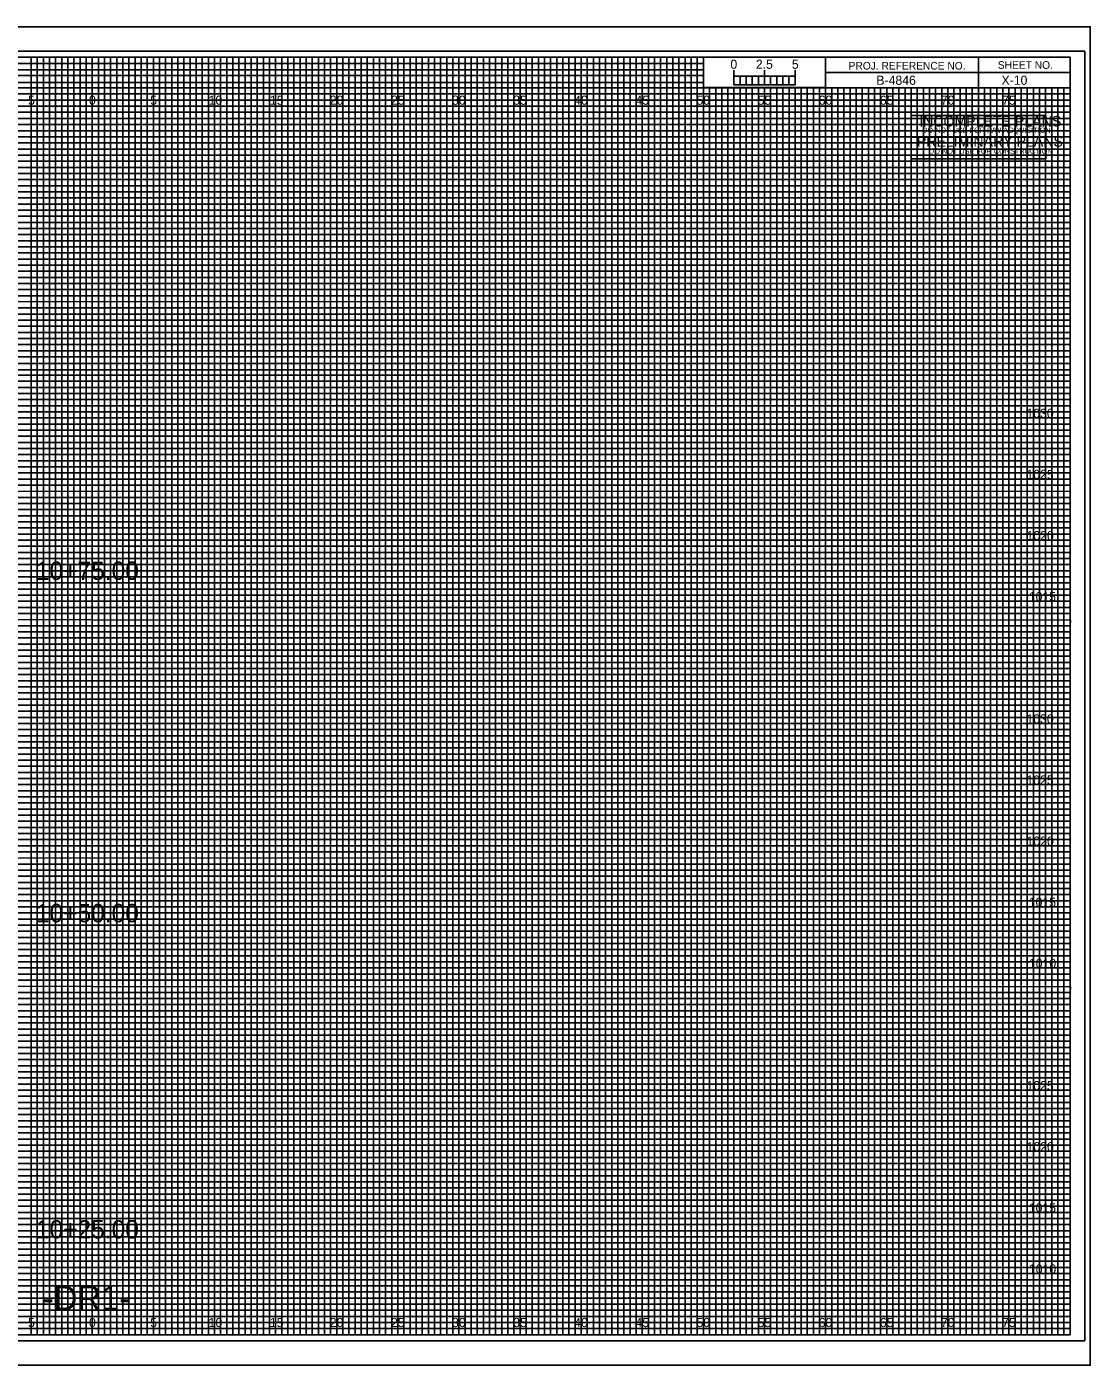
# Model space of a CAD drawing. Extents: x -7 to 162, y -2 to 107.
# Drawn here: x 74.6 to 161.7, y -2.5 to 107 of the extents above; entities that cross this region are included whole.
import ezdxf

# ---------------------------------------------------------------- set-up
doc = ezdxf.new("R2010")
doc.units = 0
for name, color, linetype in [('Default', 7, 'Continuous'), ('Exist Cross Section Cell', 7, 'Continuous'), ('Exist XS Center Line Elevation Label', 7, 'Continuous'), ('Exist XS Ground Line', 7, 'Continuous'), ('Prop CMT Concrete Structures', 7, 'Continuous'), ('Prop CMT DNC', 7, 'Continuous'), ('Prop CMT Guardrail Graphics', 7, 'Continuous'), ('Prop CMT Guardrail Widen Shoulder', 7, 'Continuous'), ('Prop CMT Pvmt Course 1', 7, 'Continuous'), ('Prop CMT Pvmt Surface', 7, 'Continuous'), ('Prop CMT Pvmt Surface Shoulder', 7, 'Continuous'), ('Prop CMT Shld Paved Course 1', 7, 'Continuous'), ('Prop CMT Shoulder Point', 7, 'Continuous'), ('Prop CMT Slope Grass', 7, 'Continuous'), ('Prop CMT Subgrade Earthwork', 7, 'Continuous'), ('Prop XS SE Text', 7, 'Continuous'), ('Prop XS Side Slope Text', 7, 'Continuous'), ('Typical Text Label CELL', 7, 'Continuous')]:
    doc.layers.add(name, color=color, linetype=linetype)

msp = doc.modelspace()

# ---------------------------------------------------------------- linework, layer by layer
at = {"layer": 'Default'}
for points in [[(146.99, 97.97), (146.99, 99.73), (158.01, 99.73), (158.01, 97.97)], [(146.99, 96.2), (146.99, 97.97), (158.01, 97.97), (158.01, 96.2)]]:
    msp.add_lwpolyline(points, close=True, dxfattribs=at)
at = {"layer": 'Exist XS Center Line Elevation Label'}
for points in [[(72.5, 0), (77.5, 0), (77.5, 104.5), (82.5, 104.5), (82.5, 0), (87.5, 0), (87.5, 104.5), (92.5, 104.5), (92.5, 0), (97.5, 0), (97.5, 104.5), (102.5, 104.5), (102.5, 0), (107.5, 0), (107.5, 104.5), (112.5, 104.5), (112.5, 0), (117.5, 0), (117.5, 104.5), (122.5, 104.5), (122.5, 0), (127.5, 0), (127.5, 104.5), (129.97, 104.5), (130, 104.5), (130, 102), (132.5, 102), (132.5, 0), (137.5, 0), (137.5, 102), (142.5, 102), (142.5, 0), (147.5, 0), (147.5, 102), (152.5, 102), (152.5, 0), (157.5, 0), (157.5, 102)], [(0, 102), (137.5, 102)], [(0, 92.5), (160, 92.5), (160, 97.5), (0, 97.5)], [(0, 82.5), (160, 82.5), (160, 87.5), (0, 87.5)], [(0, 72.5), (160, 72.5), (160, 77.5), (0, 77.5)], [(0, 62.5), (160, 62.5), (160, 67.5), (0, 67.5)], [(0, 52.5), (160, 52.5), (160, 57.5), (0, 57.5)], [(0, 42.5), (160, 42.5), (160, 47.5), (0, 47.5)], [(0, 32.5), (160, 32.5), (160, 37.5), (0, 37.5)], [(0, 22.5), (160, 22.5), (160, 27.5), (0, 27.5)], [(0, 12.5), (160, 12.5), (160, 17.5), (0, 17.5)], [(0, 2.5), (160, 2.5), (160, 7.5), (0, 7.5)]]:
    msp.add_lwpolyline(points, dxfattribs=at)
at = {"layer": 'Exist XS Ground Line'}
for p, q in [((75, 104.5), (70, 104.5)), ((75, 0), (75, 104.5)), ((85, 104.5), (80, 104.5)), ((80, 104.5), (80, 0)), ((85, 0), (85, 104.5)), ((95, 104.5), (90, 104.5)), ((90, 104.5), (90, 0)), ((95, 0), (95, 104.5)), ((105, 104.5), (100, 104.5)), ((100, 104.5), (100, 0)), ((105, 0), (105, 104.5)), ((115, 104.5), (110, 104.5)), ((110, 104.5), (110, 0)), ((115, 0), (115, 104.5)), ((125, 104.5), (120, 104.5)), ((120, 104.5), (120, 0)), ((125, 0), (125, 104.5)), ((130, 104.5), (130, 0)), ((135, 0), (135, 102)), ((145, 102), (140, 102)), ((140, 102), (140, 0)), ((145, 0), (145, 102)), ((155, 102), (150, 102)), ((150, 102), (150, 0)), ((155, 0), (155, 102)), ((80, 0), (75, 0)), ((90, 0), (85, 0)), ((100, 0), (95, 0)), ((110, 0), (105, 0)), ((120, 0), (115, 0)), ((130, 0), (125, 0)), ((140, 0), (135, 0)), ((150, 0), (145, 0)), ((160, 0), (155, 0)), ((160, 0), (160, 0))]:
    msp.add_line(p, q, dxfattribs=at)
for points in [[(0, 100), (160, 100), (160, 95), (0, 95)], [(0, 90), (160, 90), (160, 85), (0, 85)], [(0, 80), (160, 80), (160, 75), (0, 75)], [(0, 70), (160, 70), (160, 65), (0, 65)], [(0, 60), (160, 60), (160, 55), (0, 55)], [(0, 50), (160, 50), (160, 45), (0, 45)], [(0, 40), (160, 40), (160, 35), (0, 35)], [(0, 30), (160, 30), (160, 25), (0, 25)], [(0, 20), (160, 20), (160, 15), (0, 15)], [(0, 10), (160, 10), (160, 5), (0, 5)]]:
    msp.add_lwpolyline(points, dxfattribs=at)
at = {"layer": 'Prop CMT Concrete Structures'}
for p, q in [((75, 0), (75, 104.5)), ((80, 0), (80, 104.5)), ((85, 0), (85, 104.5)), ((90, 0), (90, 104.5)), ((95, 0), (95, 104.5)), ((100, 0), (100, 104.5)), ((105, 0), (105, 104.5)), ((110, 0), (110, 104.5)), ((115, 0), (115, 104.5)), ((120, 0), (120, 104.5)), ((125, 0), (125, 104.5)), ((130, 0), (130, 101.84)), ((135, 0), (135, 101.84)), ((140, 0), (140, 101.84)), ((145, 0), (145, 101.84)), ((150, 0), (150, 101.84)), ((155, 0), (155, 101.84)), ((0, 100), (160, 100)), ((0, 95), (160, 95)), ((0, 90), (160, 90)), ((0, 85), (160, 85)), ((0, 80), (160, 80)), ((0, 75), (160, 75)), ((0, 70), (160, 70)), ((0, 65), (160, 65)), ((0, 60), (160, 60)), ((0, 55), (160, 55)), ((0, 50), (160, 50)), ((0, 45), (160, 45)), ((0, 40), (160, 40)), ((0, 35), (160, 35)), ((0, 30), (160, 30)), ((0, 25), (160, 25)), ((0, 20), (160, 20)), ((0, 15), (160, 15)), ((0, 10), (160, 10)), ((0, 5), (160, 5))]:
    msp.add_line(p, q, dxfattribs=at)
at = {"layer": 'Prop CMT Guardrail Widen Shoulder'}
for p, q in [((161.65, 107), (-6.7, 107)), ((-6.7, -2.5), (161.65, -2.5))]:
    msp.add_line(p, q, dxfattribs=at)
at = {"layer": 'Prop CMT Pvmt Course 1'}
msp.add_lwpolyline([(-6.7, -2.5), (161.65, -2.5), (161.65, 107), (-6.7, 107)], close=True, dxfattribs=at)
at = {"layer": 'Prop CMT Pvmt Surface'}
for p, q in [((133.5, 102), (133, 102)), ((133, 102), (133, 0)), ((133.5, 0), (133.5, 102)), ((134.5, 102), (134, 102)), ((134, 102), (134, 0)), ((134.5, 0), (134.5, 102)), ((133, 0), (132.5, 0)), ((134, 0), (133.5, 0))]:
    msp.add_line(p, q, dxfattribs=at)
for points in [[(75, 0), (75.5, 0), (75.5, 104.5), (76, 104.5), (76, 0)], [(76, 0), (76.5, 0), (76.5, 104.5), (77, 104.5), (77, 0)], [(77.5, 0), (78, 0), (78, 104.5), (78.5, 104.5), (78.5, 0)], [(78.5, 0), (79, 0), (79, 104.5), (79.5, 104.5), (79.5, 0)], [(80, 0), (80.5, 0), (80.5, 104.5), (81, 104.5), (81, 0)], [(81, 0), (81.5, 0), (81.5, 104.5), (82, 104.5), (82, 0)], [(82.5, 0), (83, 0), (83, 104.5), (83.5, 104.5), (83.5, 0)], [(83.5, 0), (84, 0), (84, 104.5), (84.5, 104.5), (84.5, 0)], [(85, 0), (85.5, 0), (85.5, 104.5), (86, 104.5), (86, 0)], [(86, 0), (86.5, 0), (86.5, 104.5), (87, 104.5), (87, 0)], [(87.5, 0), (88, 0), (88, 104.5), (88.5, 104.5), (88.5, 0)], [(88.5, 0), (89, 0), (89, 104.5), (89.5, 104.5), (89.5, 0)], [(90, 0), (90.5, 0), (90.5, 104.5), (91, 104.5), (91, 0)], [(91, 0), (91.5, 0), (91.5, 104.5), (92, 104.5), (92, 0)], [(92.5, 0), (93, 0), (93, 104.5), (93.5, 104.5), (93.5, 0)], [(93.5, 0), (94, 0), (94, 104.5), (94.5, 104.5), (94.5, 0)], [(95, 0), (95.5, 0), (95.5, 104.5), (96, 104.5), (96, 0)], [(96, 0), (96.5, 0), (96.5, 104.5), (97, 104.5), (97, 0)], [(97.5, 0), (98, 0), (98, 104.5), (98.5, 104.5), (98.5, 0)], [(98.5, 0), (99, 0), (99, 104.5), (99.5, 104.5), (99.5, 0)], [(100, 0), (100.5, 0), (100.5, 104.5), (101, 104.5), (101, 0)], [(101, 0), (101.5, 0), (101.5, 104.5), (102, 104.5), (102, 0)], [(102.5, 0), (103, 0), (103, 104.5), (103.5, 104.5), (103.5, 0)], [(103.5, 0), (104, 0), (104, 104.5), (104.5, 104.5), (104.5, 0)], [(105, 0), (105.5, 0), (105.5, 104.5), (106, 104.5), (106, 0)], [(106, 0), (106.5, 0), (106.5, 104.5), (107, 104.5), (107, 0)], [(107.5, 0), (108, 0), (108, 104.5), (108.5, 104.5), (108.5, 0)], [(108.5, 0), (109, 0), (109, 104.5), (109.5, 104.5), (109.5, 0)], [(110, 0), (110.5, 0), (110.5, 104.5), (111, 104.5), (111, 0)], [(111, 0), (111.5, 0), (111.5, 104.5), (112, 104.5), (112, 0)], [(112.5, 0), (113, 0), (113, 104.5), (113.5, 104.5), (113.5, 0)], [(113.5, 0), (114, 0), (114, 104.5), (114.5, 104.5), (114.5, 0)], [(115, 0), (115.5, 0), (115.5, 104.5), (116, 104.5), (116, 0)], [(116, 0), (116.5, 0), (116.5, 104.5), (117, 104.5), (117, 0)], [(117.5, 0), (118, 0), (118, 104.5), (118.5, 104.5), (118.5, 0)], [(118.5, 0), (119, 0), (119, 104.5), (119.5, 104.5), (119.5, 0)], [(120, 0), (120.5, 0), (120.5, 104.5), (121, 104.5), (121, 0)], [(121, 0), (121.5, 0), (121.5, 104.5), (122, 104.5), (122, 0)], [(122.5, 0), (123, 0), (123, 104.5), (123.5, 104.5), (123.5, 0)], [(123.5, 0), (124, 0), (124, 104.5), (124.5, 104.5), (124.5, 0)], [(125, 0), (125.5, 0), (125.5, 104.5), (126, 104.5), (126, 0)], [(126, 0), (126.5, 0), (126.5, 104.5), (127, 104.5), (127, 0)], [(127.5, 0), (128, 0), (128, 104.5), (128.5, 104.5), (128.5, 0)], [(128.5, 0), (129, 0), (129, 104.5), (129.5, 104.5), (129.5, 0)], [(130, 0), (130.5, 0), (130.5, 102), (131.01, 102), (131.01, 0)], [(131, 0), (131.5, 0), (131.5, 102), (132, 102), (132, 0)], [(135, 0), (135.49, 0), (135.49, 102), (136, 102), (136, 0)], [(136, 0), (136.5, 0), (136.5, 102), (137.03, 102), (137.03, 0)], [(137.5, 0), (138, 0), (138, 102), (138.5, 102), (138.5, 0)], [(138.5, 0), (139, 0), (139, 102), (139.5, 102), (139.5, 0)], [(140, 0), (140.5, 0), (140.5, 102), (141, 102), (141, 0)], [(141, 0), (141.5, 0), (141.5, 102), (142, 102), (142, 0)], [(142.5, 0), (143, 0), (143, 102), (143.5, 102), (143.5, 0)], [(143.5, 0), (144, 0), (144, 102), (144.5, 102), (144.5, 0)], [(145, 0), (145.5, 0), (145.5, 102), (146, 102), (146, 0)], [(146, 0), (146.5, 0), (146.5, 102), (147, 102), (147, 0)], [(147.5, 0), (148, 0), (148, 102), (148.5, 102), (148.5, 0)], [(148.5, 0), (149, 0), (149, 102), (149.5, 102), (149.5, 0)], [(150, 0), (150.5, 0), (150.5, 102), (151, 102), (151, 0)], [(151, 0), (151.5, 0), (151.5, 102), (152, 102), (152, 0)], [(152.5, 0), (153, 0), (153, 102), (153.5, 102), (153.5, 0)], [(153.5, 0), (154, 0), (154, 102), (154.5, 102), (154.5, 0)], [(155, 0), (155.5, 0), (155.5, 102), (156, 102), (156, 0)], [(156, 0), (156.5, 0), (156.5, 102), (157, 102), (157, 0)], [(157.5, 0), (158, 0), (158, 102), (158.5, 102), (158.5, 0)], [(158.5, 0), (159, 0), (159, 102), (159.5, 102), (159.5, 0)]]:
    msp.add_lwpolyline(points, dxfattribs=at)
at = {"layer": 'Prop CMT Pvmt Surface Shoulder'}
for p, q in [((132.5, 102.25), (132.5, 103.45)), ((132.5, 102.95), (132.5, 103.45)), ((135, 102.25), (135, 103.45)), ((137.5, 102.25), (137.5, 103.45)), ((137.5, 102.95), (137.5, 103.45))]:
    msp.add_line(p, q, dxfattribs=at)
for points in [[(137.5, 102.95), (132.5, 102.95), (132.5, 102.25), (137.5, 102.25)], [(132.5, 102.95), (133, 102.95), (133, 102.25), (132.5, 102.25)], [(133.5, 102.95), (134, 102.95), (134, 102.25), (133.5, 102.25)], [(134.5, 102.95), (135, 102.95), (135, 102.25), (134.5, 102.25)], [(135.5, 102.95), (136, 102.95), (136, 102.25), (135.5, 102.25)], [(136.5, 102.95), (137, 102.95), (137, 102.25), (136.5, 102.25)]]:
    msp.add_lwpolyline(points, close=True, dxfattribs=at)
at = {"layer": 'Prop CMT Shld Paved Course 1'}
for p, q in [((0, 104), (130, 104)), ((130, 103.49), (0, 103.49)), ((0, 103), (130, 103)), ((130, 104), (130, 103.49)), ((130, 103), (130, 102.45)), ((130, 102.45), (0, 102.45)), ((0, 101.5), (160, 101.5))]:
    msp.add_line(p, q, dxfattribs=at)
for points in [[(0, 101), (135, 101), (160, 101), (160, 101), (0, 101)], [(0, 100.5), (160, 100.5), (160, 99.5), (0, 99.5)], [(0, 99), (160, 99), (160, 98.5), (0, 98.49)], [(0, 98), (160, 98), (160, 97), (0, 97)], [(0, 96.5), (160, 96.5), (160, 96), (0, 96)], [(0, 95.5), (160, 95.5), (160, 94.5), (0, 94.5)], [(0, 94), (160, 94), (160, 93.5), (0, 93.5)], [(0, 93), (160, 93), (160, 92), (0, 92)], [(0, 91.5), (160, 91.5), (160, 91), (0, 91)], [(0, 90.5), (160, 90.5), (160, 89.5), (0, 89.5)], [(0, 89), (160, 89), (160, 88.5), (0, 88.5)], [(0, 88), (160, 88), (160, 86.98), (160, 86.5), (160, 86), (0, 86)], [(0, 87), (160, 87), (160, 86.5), (0, 86.5)], [(0, 85.5), (160, 85.5), (160, 84.5), (0, 84.52)], [(0, 84.52), (160, 84.5), (160, 84), (0, 84)], [(0, 83.5), (160, 83.5), (160, 83), (0, 83)], [(0, 82), (160, 82), (160, 81.5), (0, 81.5)], [(0, 81), (160, 81), (160, 80.5), (0, 80.5)], [(-0.04, 79.45), (160, 79.45), (160, 78.94), (-0.04, 78.94)], [(0, 78.5), (160, 78.5), (160, 78), (0, 78)], [(0, 77), (160, 77), (160, 76.5), (0, 76.5)], [(0, 76), (160, 76), (160, 75.5), (0, 75.5)], [(0, 74.5), (160, 74.5), (160, 74), (0, 74)], [(0, 73.5), (160, 73.5), (160, 73), (0, 73)], [(0, 72), (160, 72), (160, 71.5), (0, 71.5)], [(0, 71), (160, 71), (160, 70.5), (0, 70.5)], [(0, 69.5), (160, 69.5), (160, 68.99), (0, 69)], [(0, 68.5), (160, 68.5), (160, 68), (0, 68)], [(0, 67), (160, 67), (160, 66.5), (0, 66.5)], [(0, 66), (160, 66), (160, 65.5), (0, 65.5)], [(0, 64.5), (160, 64.5), (160, 64), (0, 64)], [(0, 63.5), (160, 63.5), (160, 63), (0, 63)], [(0, 62), (160, 62), (160, 61.5), (0, 61.5)], [(0, 61), (160, 61), (160, 60.5), (0, 60.5)], [(0, 59.5), (160, 59.5), (160, 59), (0, 59)], [(0, 58.5), (160.03, 58.45), (160, 58), (0, 58)], [(0, 57), (160, 57), (160, 56.5), (0, 56.5)], [(0, 56), (160, 56), (160, 55.5), (0, 55.5)], [(0, 54.5), (160, 54.5), (160, 54), (0, 54)], [(0, 53.5), (160, 53.5), (160, 53), (0, 53)], [(0, 52), (160, 52), (160, 51.5), (0, 51.5)], [(0, 51), (160, 51), (160, 50.5), (0, 50.5)], [(0, 49.5), (160, 49.5), (160, 49), (0, 49)], [(0, 48.5), (160, 48.5), (160, 48), (0, 48)], [(0, 47), (160, 47), (160, 46.5), (0, 46.5)], [(0, 46), (160, 46), (160, 45.5), (0, 45.5)], [(0, 44.5), (160, 44.5), (160, 44), (0, 44)], [(0, 43.5), (160, 43.5), (160, 43), (0, 43)], [(0, 42), (160, 42), (160, 41.5), (0, 41.5)], [(0, 41), (160, 41), (160, 40.5), (0, 40.5)], [(0, 39.5), (160, 39.5), (160, 38.99), (0, 39)], [(0, 38.5), (160, 38.5), (160, 38), (0, 38)], [(0, 37), (160, 37), (160, 36.5), (0, 36.5)], [(0, 36), (160, 36), (160, 35.5), (0, 35.5)], [(0, 34.5), (160, 34.5), (160, 34), (0, 34)], [(0, 33.5), (160, 33.5), (160, 33), (0, 33)], [(0, 32), (160, 32), (160, 31.5), (0, 31.5)], [(0, 31), (160, 31), (160, 30.5), (0, 30.5)], [(0, 29.5), (160, 29.5), (160, 29), (0, 29)], [(0, 28.5), (160.03, 28.46), (160, 28), (0, 28)], [(0, 27), (160, 27), (160, 26.5), (0, 26.5)], [(0, 26), (160, 26), (160, 25.5), (0, 25.5)], [(0, 24.5), (160, 24.5), (160, 24), (0, 24)], [(0, 23.5), (160, 23.5), (160, 23), (0, 23)], [(0, 22), (160, 22), (160, 21.5), (0, 21.5)], [(0, 21), (160, 21), (160, 20.5), (0, 20.5)], [(0, 19.5), (160, 19.5), (160, 19), (0, 19)], [(0, 18.5), (160, 18.5), (160, 18), (0, 18)], [(0, 17), (160, 17), (160, 16.5), (0, 16.5)], [(0, 16), (160, 16), (160, 15.5), (0, 15.5)], [(0, 14.5), (160, 14.5), (160, 14), (0, 14)], [(0, 13.5), (160, 13.5), (160, 13), (0, 13)], [(0, 12), (160, 12), (160, 11.5), (0, 11.5)], [(0, 11), (160, 11), (160, 10.5), (0, 10.5)], [(0, 9.5), (160, 9.5), (160, 9), (0, 9)], [(0, 8.5), (160, 8.5), (160, 8), (0, 8)], [(0, 7), (160, 7), (160, 6.5), (0, 6.5)], [(0, 6), (160, 6), (160, 5.5), (0, 5.5)], [(0, 4.5), (160, 4.5), (160, 4), (0, 4)], [(0, 3.5), (160, 3.5), (160, 3), (0, 3)], [(0, 2), (160, 2), (160, 1.5), (0, 1.5)], [(0, 1), (160, 1), (160, 0.5), (0, 0.5)]]:
    msp.add_lwpolyline(points, dxfattribs=at)
at = {"layer": 'Prop CMT Slope Grass'}
msp.add_lwpolyline([(-5.4, -0.5), (161.2, -0.5), (161.2, 105), (-5.4, 105)], close=True, dxfattribs=at)
at = {"layer": 'Prop CMT Subgrade Earthwork'}
for p, q in [((152.5, 104.5), (152.5, 102)), ((152.5, 102), (152.5, 104.5)), ((160, 103.25), (140, 103.25)), ((140, 103.25), (140, 102)), ((140, 102), (160, 102))]:
    msp.add_line(p, q, dxfattribs=at)
for points in [[(160, 104.5), (0, 104.5), (0, 0), (160, 0)], [(140, 104.5), (130, 104.5), (130, 102.02), (140, 102.02)], [(160, 104.5), (140, 104.5), (140, 102), (160, 102)]]:
    msp.add_lwpolyline(points, close=True, dxfattribs=at)

# ---------------------------------------------------------------- texts
at = {"layer": 'Default'}
for s, height, p in [('INCOMPLETE PLANS', 0.864, (147.66, 98.84)), ('DO NOT USE FOR R/W ACQUISITION', 0.432, (147.9, 98.32)), ('PRELIMINARY PLANS', 0.864, (147.47, 97.19)), ('DO NOT USE FOR CONSTRUCTION', 0.432, (148.46, 96.61))]:
    msp.add_text(s, height=height, dxfattribs=at).set_placement(p)
at = {"layer": 'Exist Cross Section Cell'}
for s, p in [('5', (74.74, 100.62)), ('0', (79.73, 100.62)), ('0', (79.73, 100.62)), ('5', (84.74, 100.62)), ('10', (89.52, 100.62)), ('15', (94.53, 100.62)), ('20', (99.43, 100.62)), ('25', (104.44, 100.62)), ('30', (109.43, 100.62)), ('35', (114.44, 100.62)), ('40', (119.43, 100.62)), ('45', (124.44, 100.62)), ('50', (129.43, 100.62)), ('55', (134.44, 100.62)), ('60', (139.43, 100.62)), ('65', (144.44, 100.62)), ('70', (149.43, 100.62)), ('75', (154.44, 100.62)), ('5', (74.74, 0.62)), ('0', (79.73, 0.62)), ('0', (79.73, 0.62)), ('5', (84.74, 0.62)), ('10', (89.52, 0.62)), ('15', (94.53, 0.62)), ('20', (99.43, 0.62)), ('25', (104.44, 0.62)), ('30', (109.43, 0.62)), ('35', (114.44, 0.62)), ('40', (119.43, 0.62)), ('45', (124.44, 0.62)), ('50', (129.43, 0.62)), ('55', (134.44, 0.62)), ('60', (139.43, 0.62)), ('65', (144.44, 0.62)), ('70', (149.43, 0.62)), ('75', (154.44, 0.62))]:
    msp.add_text(s, height=0.75, dxfattribs=at).set_placement(p)
at = {"layer": 'Prop CMT DNC'}
msp.add_text('-DR1-', height=2, dxfattribs=at).set_placement((75.96, 2))
at = {"layer": 'Prop CMT Guardrail Graphics'}
msp.add_text('B-4846', height=0.75, dxfattribs=at).set_placement((144.15, 102.25))
at = {"layer": 'Prop CMT Pvmt Surface Shoulder'}
msp.add_text('0', height=0.75, dxfattribs=at).set_placement((132.21, 103.56))
at = {"layer": 'Prop CMT Shoulder Point'}
for s, p in [('2.5', (134.29, 103.56)), ('5', (137.24, 103.56))]:
    msp.add_text(s, height=0.75, dxfattribs=at).set_placement(p)
at = {"layer": 'Prop CMT Subgrade Earthwork'}
for s, p in [('PROJ. REFERENCE NO.', (141.88, 103.5)), ('SHEET NO.', (154.09, 103.56))]:
    msp.add_text(s, height=0.625, dxfattribs=at).set_placement(p)
at = {"layer": 'Prop XS SE Text'}
msp.add_text('X-10', height=0.75, dxfattribs=at).set_placement((154.39, 102.25))
at = {"layer": 'Prop XS Side Slope Text'}
for s, p in [('10+75.00', (75.39, 61.75)), ('10+50.00', (75.39, 33.74)), ('10+25.00', (75.39, 7.87))]:
    msp.add_text(s, height=1.5, dxfattribs=at).set_placement(p)
at = {"layer": 'Typical Text Label CELL'}
for s, p in [('1030', (156.43, 75)), ('1025', (156.43, 70)), ('1020', (156.44, 65)), ('1015', (156.62, 60)), ('1030', (156.43, 50)), ('1025', (156.43, 45)), ('1020', (156.44, 40)), ('1015', (156.62, 35)), ('1010', (156.63, 30)), ('1025', (156.43, 20)), ('1020', (156.44, 15)), ('1015', (156.62, 10)), ('1010', (156.63, 5))]:
    msp.add_text(s, height=0.75, dxfattribs=at).set_placement(p)

doc.saveas('drawing.dxf')
